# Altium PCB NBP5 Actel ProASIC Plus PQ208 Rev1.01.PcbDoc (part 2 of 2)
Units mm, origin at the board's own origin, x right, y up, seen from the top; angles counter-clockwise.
Board outline 69 x 80.99 mm, 2 copper layers (Top Layer, Bottom Layer); 65 components, 193 nets, 558 pads, 171 vias.
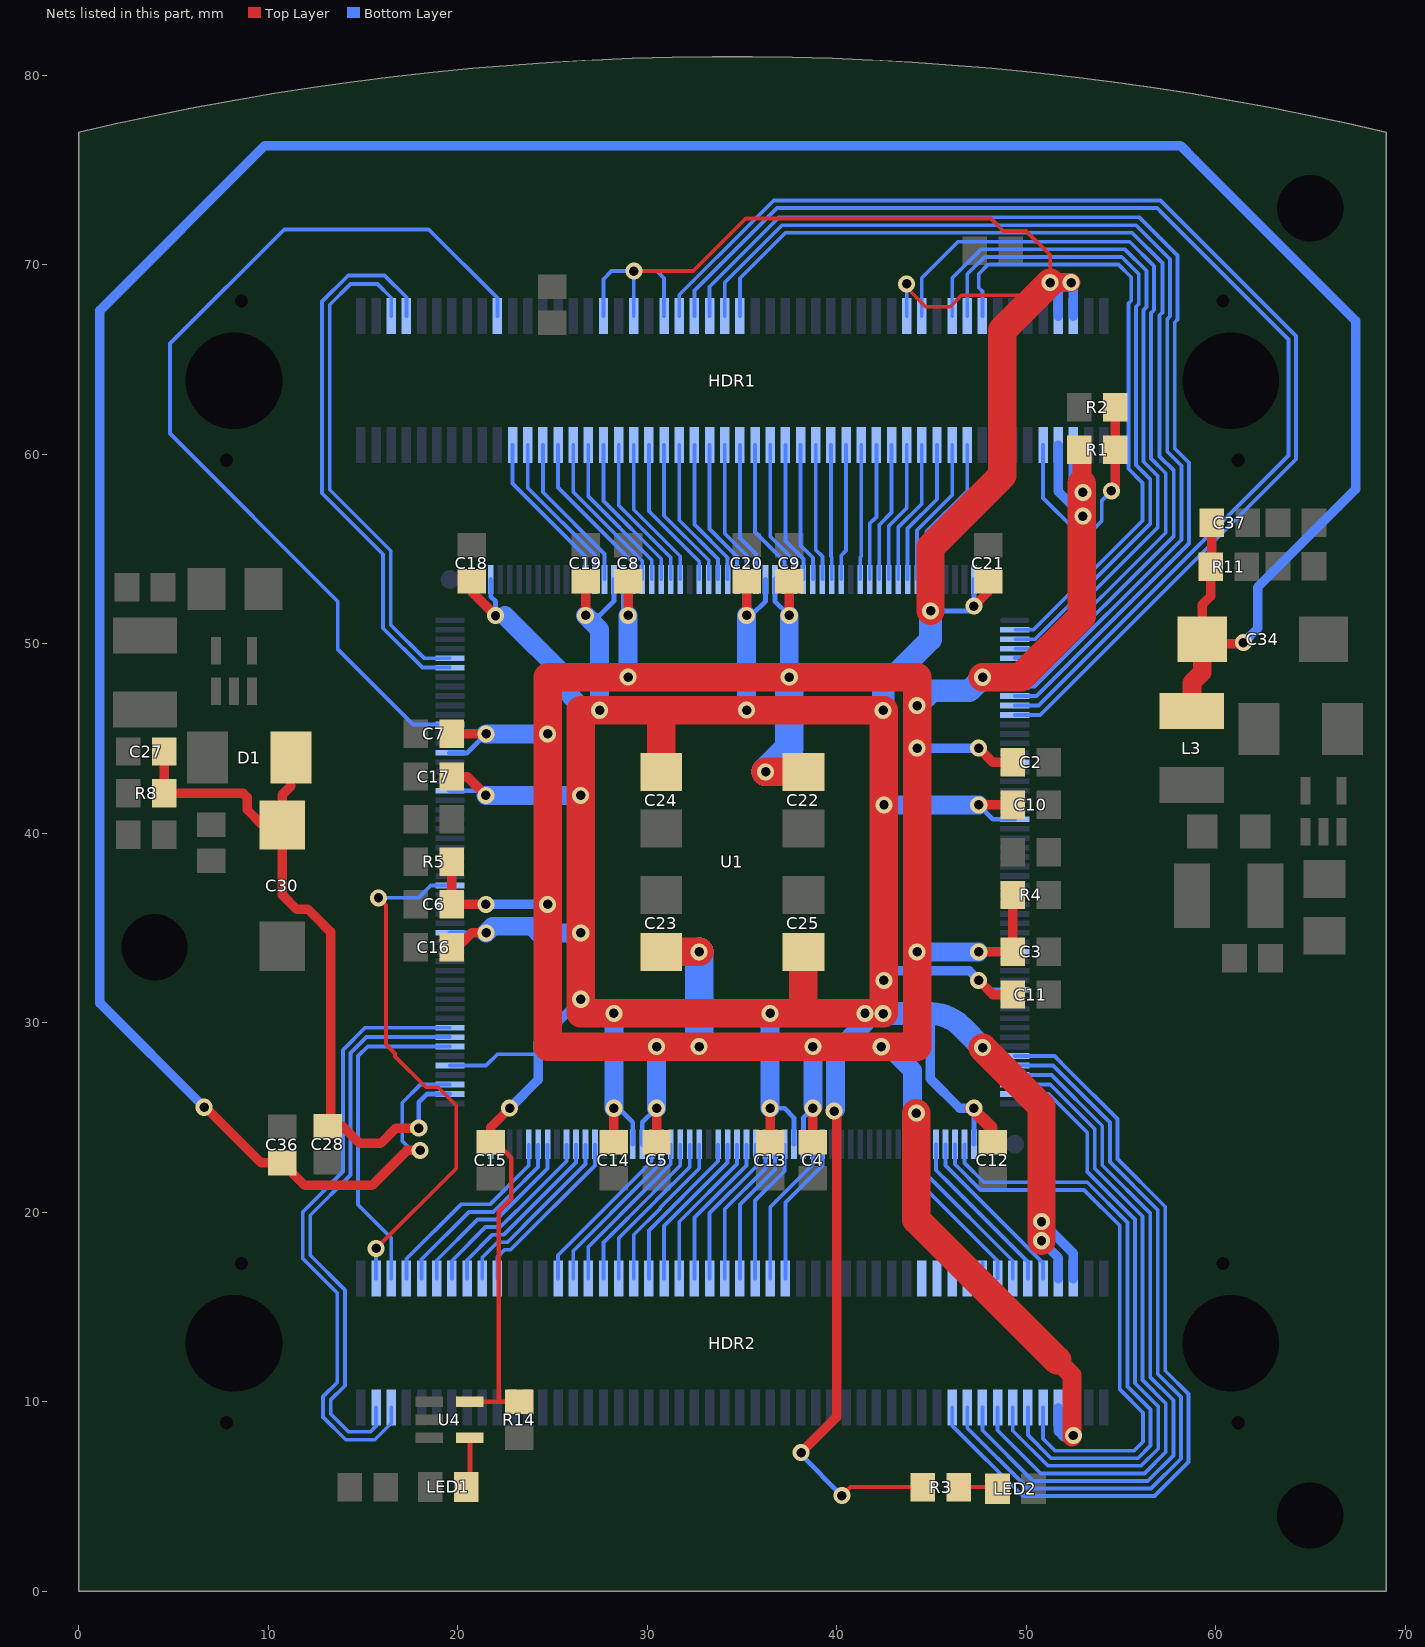
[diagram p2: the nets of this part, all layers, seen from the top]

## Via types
v1: diameter 0.9, hole 0.5, Top Layer to Bottom Layer, tented bottom, 171 vias

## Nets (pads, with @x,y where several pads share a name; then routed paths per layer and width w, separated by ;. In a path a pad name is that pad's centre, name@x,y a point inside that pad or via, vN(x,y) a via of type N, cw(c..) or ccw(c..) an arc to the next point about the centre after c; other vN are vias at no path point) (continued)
NetLED1_2: LED1.2 U4.4 | length 2.7
  Top Layer w0.25: LED1.2@20.457,5.512 20.65,5.705 U4.4@20.65,8.1
NetLED2_1: LED2.1 R3.2 | length 2.1
  Top Layer w0.2: R3.2@46.45,5.503 48.398,5.503 LED2.1@48.492,5.408
NEXUS_TCK: HDR1.82 U1.3 | length 35.2
  Bottom Layer w0.2: HDR1.82@46.9,67.3 46.9,69.525 47.8,70.425 55.05,70.425 55.95,69.525 55.95,67.947 55.8,67.797 55.8,59.45 56.55,58.7 56.55,56.325 50.475,50.25 U1.3@49.425,50.25
NEXUS_TDI: HDR1.84 U1.2 | length 34.1
  Bottom Layer w0.2: HDR1.84@47.7,68.2 HDR1.84@47.7,67.3 47.7,68.6 47.5,68.8 47.5,69.525 48,70.025 54.875,70.025 55.55,69.35 55.55,68.113 55.4,67.963 55.4,59.25 56.15,58.5 56.15,56.5 50.4,50.75 U1.2@49.425,50.75
NEXUS_TDO: HDR1.76 U1.5 | length 40.8
  Bottom Layer w0.2: HDR1.76@44.5,67.3 44.5,69.325 46.4,71.225 55.475,71.225 56.75,69.95 56.75,67.616 56.6,67.466 56.6,59.781 57.371,59.01 57.371,55.871 50.751,49.251 U1.5@49.4,49.251
NEXUS_TMS: HDR1.80 U1.4 | length 37.4
  Bottom Layer w0.2: HDR1.80@46.1,67.3 46.1,69.3 47.625,70.825 55.225,70.825 56.35,69.7 56.35,67.781 56.2,67.631 56.2,59.616 56.95,58.866 56.95,56.15 50.55,49.75 U1.4@49.425,49.75
RAM0_DATA0: HDR2.42 U1.79 | length 8.5
  Bottom Layer w0.2: HDR2.42@30.9,16.5 30.9,19.275 34.25,22.625 U1.79@34.25,23.575
RAM0_DATA1: HDR2.40 U1.80 | length 8.6
  Bottom Layer w0.2: HDR2.40@30.1,16.5 30.1,19.05 33.75,22.7 U1.80@33.75,23.575
RAM0_DATA2: HDR2.38 U1.82 | length 8.5
  Bottom Layer w0.2: HDR2.38@29.3,16.5 29.3,18.816 30.7,20.216 30.7,20.275 32.75,22.325 U1.82@32.75,23.575
RAM0_DATA3: HDR2.36 U1.83 | length 8.6
  Bottom Layer w0.2: HDR2.36@28.5,16.5 28.5,18.641 30.525,20.666 30.525,20.675 32.25,22.4 U1.83@32.25,23.575
RAM0_DATA4: HDR2.34 U1.84 | length 8.8
  Bottom Layer w0.2: HDR2.34@27.7,16.5 27.7,18.416 30.35,21.066 30.35,21.075 31.75,22.475 U1.84@31.75,23.575
RAM0_DATA5: HDR2.32 U1.85 | length 8.9
  Bottom Layer w0.2: HDR2.32@26.9,16.5 26.9,18.191 30.175,21.466 30.175,21.475 31.25,22.55 U1.85@31.25,23.575
RAM0_DATA6: HDR2.30 U1.86 | length 9
  Bottom Layer w0.2: HDR2.30@26.1,16.5 26.1,17.966 30,21.866 30,21.875 30.75,22.625 U1.86@30.75,23.575
RAM0_DATA7: HDR2.28 U1.87 | length 9.1
  Bottom Layer w0.2: HDR2.28@25.3,16.5 25.3,17.741 29.825,22.266 29.825,22.275 30.25,22.7 U1.87@30.25,23.575
RAM0_OE: HDR1.41 U1.180 | length 8
  Bottom Layer w0.2: HDR1.41@30.9,60.5 30.9,56.766 33.25,54.416 U1.180@33.25,53.425
RAM0_WE: HDR1.79 U1.202 | length 7.8
  Bottom Layer w0.2: U1.202@44.25,53.425 44.25,56 46.1,57.85 HDR1.79@46.1,60.5
RAM1_DATA0: HDR1.45 U1.182 | length 7.8
  Bottom Layer w0.2: HDR1.45@32.5,60.5 32.5,56.297 34.25,54.547 U1.182@34.25,53.425
RAM1_DATA1: HDR1.49 U1.184 | length 7.6
  Bottom Layer w0.2: HDR1.49@34.1,60.5 34.1,55.828 35.25,54.678 U1.184@35.25,53.425
RAM1_DATA2: HDR1.53 U1.188 | length 7.7
  Bottom Layer w0.2: HDR1.53@35.7,60.5 35.7,55.9 37.25,54.35 U1.188@37.25,53.425
RAM1_DATA3: HDR1.57 U1.190 | length 7.5
  Bottom Layer w0.2: HDR1.57@37.3,60.5 37.3,55.431 38.25,54.481 U1.190@38.25,53.425
RAM1_DATA4: HDR1.55 U1.189 | length 7.6
  Bottom Layer w0.2: HDR1.55@36.5,60.5 36.5,55.666 37.75,54.416 U1.189@37.75,53.425
RAM1_DATA5: HDR1.51 U1.185 | length 7.4
  Bottom Layer w0.2: HDR1.51@34.9,60.5 34.9,55.594 35.75,54.744 U1.185@35.75,53.425
RAM1_DATA6: HDR1.47 U1.183 | length 7.7
  Bottom Layer w0.2: HDR1.47@33.3,60.5 33.3,56.063 34.75,54.613 U1.183@34.75,53.425
RAM1_DATA7: HDR1.43 U1.181 | length 7.9
  Bottom Layer w0.2: HDR1.43@31.7,60.5 31.7,56.531 33.75,54.481 U1.181@33.75,53.425
RAM1_OE: HDR1.39 U1.179 | length 8.2
  Bottom Layer w0.2: HDR1.39@30.1,60.5 30.1,57 32.75,54.35 U1.179@32.75,53.425
RAM1_WE: HDR1.61 U1.192 | length 7.2
  Bottom Layer w0.2: HDR1.61@38.9,60.5 38.9,54.963 39.25,54.613 U1.192@39.25,53.425
RAM_ADDR0: HDR1.21 U1.167 | length 8.7
  Bottom Layer w0.2: HDR1.21@22.9,60.5 22.9,58.472 26.75,54.622 U1.167@26.75,53.425
RAM_ADDR1: HDR1.25 U1.169 | length 8.4
  Bottom Layer w0.2: HDR1.25@24.5,60.5 24.5,58.003 27.75,54.753 U1.169@27.75,53.425
RAM_ADDR2: HDR1.29 U1.173 | length 8.6
  Bottom Layer w0.2: HDR1.29@26.1,60.5 26.1,58.016 29.75,54.366 U1.173@29.75,53.425
RAM_ADDR3: HDR1.33 U1.175 | length 8.3
  Bottom Layer w0.2: HDR1.33@27.7,60.5 27.7,57.547 30.75,54.497 U1.175@30.75,53.425
RAM_ADDR4: HDR1.65 U1.194 | length 7.2
  Bottom Layer w0.2: U1.194@40.25,53.425 40.25,54.675 40.5,54.925 HDR1.65@40.5,60.5
RAM_ADDR5: HDR1.69 U1.197 | length 7.2
  Bottom Layer w0.2: U1.197@41.75,53.425 41.75,56.35 42.1,56.7 HDR1.69@42.1,60.5
RAM_ADDR6: HDR1.73 U1.199 | length 7.5
  Bottom Layer w0.2: U1.199@42.75,53.425 42.75,56.219 43.7,57.169 HDR1.73@43.7,60.5
RAM_ADDR7: HDR1.77 U1.201 | length 7.7
  Bottom Layer w0.2: U1.201@43.75,53.425 43.75,56.087 45.3,57.637 HDR1.77@45.3,60.5
RAM_ADDR8: HDR1.75 U1.200 | length 7.6
  Bottom Layer w0.2: U1.200@43.25,53.425 43.25,56.153 44.5,57.403 HDR1.75@44.5,60.5
RAM_ADDR9: HDR1.71 U1.198 | length 7.3
  Bottom Layer w0.2: U1.198@42.25,53.425 42.25,56.284 42.9,56.934 HDR1.71@42.9,60.5
RAM_ADDR10: HDR1.67 U1.196 | length 7.1
  Bottom Layer w0.2: U1.196@41.25,53.425 41.25,54.575 41.3,54.625 HDR1.67@41.3,60.5
RAM_ADDR11: HDR1.63 U1.193 | length 7.1
  Bottom Layer w0.2: HDR1.63@39.7,60.5 39.7,54.625 39.75,54.575 U1.193@39.75,53.425
RAM_ADDR12: HDR1.59 U1.191 | length 7.3
  Bottom Layer w0.2: HDR1.59@38.1,60.5 38.1,55.197 38.75,54.547 U1.191@38.75,53.425
RAM_ADDR13: HDR1.35 U1.176 | length 8.2
  Bottom Layer w0.2: HDR1.35@28.5,60.5 28.5,57.313 31.25,54.563 U1.176@31.25,53.425
RAM_ADDR14: HDR1.31 U1.174 | length 8.5
  Bottom Layer w0.2: HDR1.31@26.9,60.5 26.9,57.781 30.25,54.431 U1.174@30.25,53.425
RAM_ADDR15: HDR1.27 U1.172 | length 8.7
  Bottom Layer w0.2: HDR1.27@25.3,60.5 25.3,58.25 29.25,54.3 U1.172@29.25,53.425
RAM_ADDR16: HDR1.23 U1.168 | length 8.5
  Bottom Layer w0.2: HDR1.23@23.7,60.5 23.7,58.238 27.25,54.688 U1.168@27.25,53.425
RAM_CS: HDR1.37 U1.177 | length 8.1
  Bottom Layer w0.2: HDR1.37@29.3,60.5 29.3,57.078 31.75,54.628 U1.177@31.75,53.425
RED0: HDR1.6 U1.152 | length 27
  Bottom Layer w0.2: HDR1.6@16.5,67.3 16.5,68.275 15.775,69 14.35,69 13.25,67.9 13.25,58.134 16.469,54.915 16.469,51.006 18.225,49.25 U1.152@19.575,49.25
RED1: HDR1.8 U1.151 | length 29.4
  Bottom Layer w0.2: HDR1.8@17.3,67.3 17.3,68.3 16.15,69.45 14.225,69.45 12.85,68.075 12.85,57.95 16.069,54.731 16.069,50.831 18.15,48.75 U1.151@19.575,48.75
REF_CLK: HDR2.4 U1.128 | length 27.9
  Top Layer w0.2: v1(15.7,18.1) 19.925,22.325 19.925,25.634 18.959,26.6 18.325,26.6 16.7,28.225 16.7,28.391 16.225,28.866 16.225,36.2 v1(15.825,36.6)
  Bottom Layer w0.2: HDR2.4@15.7,16.5 v1(15.7,18.1) ; v1(15.825,36.6) 17.934,36.6 18.584,37.25 U1.128@19.575,37.25
SCL: HDR2.5 U1.113 | length 32.7
  Bottom Layer w0.2: HDR2.5@16.5,9.7 16.5,8.875 15.625,8 14.1,8 12.9,9.2 12.9,10.275 13.65,11.025 13.65,15.744 11.825,17.569 11.825,20.025 13.95,22.15 13.95,28.577 15.123,29.75 U1.113@19.575,29.75
SDA: HDR2.3 U1.112 | length 30.4
  Bottom Layer w0.2: HDR2.3@15.7,9.7 15.7,8.725 15.402,8.427 14.248,8.427 13.3,9.375 13.3,10.1 14.05,10.85 14.05,15.91 12.225,17.735 12.225,19.85 14.35,21.975 14.35,28.412 15.188,29.25 U1.112@19.575,29.25
SP0: HDR2.79 U1.47 | length 42.2
  Bottom Layer w0.2: HDR2.79@46.1,9.7 46.1,8.75 49.825,5.025 56.775,5.025 58.575,6.825 58.575,10.419 57.35,11.644 57.35,20.294 54.825,22.819 54.825,24.925 52.246,27.504 51.499,28.251 U1.47@49.4,28.251
SP1: HDR2.81 U1.48 | length 39.9
  Bottom Layer w0.2: HDR2.81@46.9,9.7 46.9,8.625 50.1,5.425 56.6,5.425 58.175,7 58.175,10.253 56.95,11.478 56.95,20.128 54.425,22.653 54.425,24.75 51.424,27.751 U1.48@49.4,27.751
SP2: HDR2.83 U1.49 | length 37.6
  Bottom Layer w0.2: HDR2.83@47.7,9.7 47.7,8.5 50.375,5.825 56.425,5.825 57.775,7.175 57.775,10.088 56.55,11.313 56.55,19.962 54.025,22.487 54.025,24.575 51.349,27.251 U1.49@49.4,27.251
SP3: HDR2.85 U1.50 | length 35.3
  Bottom Layer w0.2: HDR2.85@48.5,9.7 48.5,8.5 50.775,6.225 56.25,6.225 57.375,7.35 57.375,9.922 56.15,11.147 56.15,19.797 53.625,22.322 53.625,24.4 51.274,26.751 U1.50@49.4,26.751
SP4: HDR2.87 U1.51 | length 33
  Bottom Layer w0.2: HDR2.87@49.3,9.7 49.3,8.475 51.15,6.625 56.075,6.625 56.975,7.525 56.975,9.756 55.75,10.981 55.75,19.631 53.225,22.156 53.225,24.225 51.199,26.251 U1.51@49.4,26.251
SP5: HDR2.89 U1.54 | length 31.9
  Bottom Layer w0.2: U1.54@46.75,23.601 46.75,22.607 47.769,21.588 53.227,21.588 55.35,19.465 55.35,10.816 56.575,9.591 56.575,7.7 55.9,7.025 51.325,7.025 50.1,8.25 HDR2.89@50.1,9.7
SP6: HDR2.91 U1.55 | length 30.4
  Bottom Layer w0.2: U1.55@46.25,23.601 46.25,22.541 47.603,21.188 53.062,21.188 54.95,19.3 54.95,10.65 56.175,9.425 56.175,7.9 55.7,7.425 51.525,7.425 50.9,8.05 HDR2.91@50.9,9.7
SP7: HDR2.92 U1.56 | length 9.2
  Bottom Layer w0.2: U1.56@45.75,23.601 45.75,22.475 50.9,17.325 HDR2.92@50.9,16.5
SP8: HDR2.90 U1.57 | length 9.4
  Bottom Layer w0.2: U1.57@45.25,23.601 45.25,22.225 45.985,21.49 ; 45.75,21.725 45.985,21.49 ; HDR2.90@50.1,16.5 50.1,17.375 45.985,21.49
SP9: HDR2.88 U1.58 | length 9
  Bottom Layer w0.2: U1.58@44.75,23.601 44.75,22 49.3,17.45 HDR2.88@49.3,16.5
SP10: HDR2.86 U1.59 | length 8.9
  Bottom Layer w0.2: U1.59@44.25,23.601 44.25,21.7 48.5,17.45 HDR2.86@48.5,16.5
SP11: HDR2.84 | length 0.8
  Bottom Layer w0.2: HDR2.84@47.7,16.5 HDR2.84@47.7,17.341
SP12: HDR2.82
SP13: HDR2.80
SP14: HDR2.78
SP15: HDR2.76
SPI_CLK: HDR1.46 U1.10 | length 63.4
  Bottom Layer w0.2: HDR1.46@32.5,67.3 32.5,68.65 36.277,72.427 36.85,73 56.925,73 57.173,72.752 63.85,66.075 63.85,59.95 50.651,46.751 U1.10@49.4,46.751
SPI_DIN: HDR1.44 U1.11 | length 66.3
  Bottom Layer w0.2: HDR1.44@31.7,67.3 31.7,68.425 35.6,72.325 ; 35.134,71.859 35.143,71.859 36.684,73.4 57.1,73.4 64.25,66.25 64.25,59.75 50.751,46.251 U1.11@49.4,46.251
SPI_DOUT: HDR1.50 U1.8 | length 54.5
  Bottom Layer w0.2: HDR1.50@34.1,67.3 34.1,69.075 36.815,71.79 37.125,72.1 55.8,72.1 57.6,70.3 57.6,67.291 57.459,67.15 ; U1.8@49.4,47.751 50.451,47.751 58.2,55.5 58.2,59.4 57.45,60.15 57.45,67.15 57.455,67.155
SPI_MODE: HDR1.52 U1.7 | length 52.2
  Bottom Layer w0.2: HDR1.52@34.9,67.3 34.9,69.3 37.3,71.7 55.6,71.7 57.2,70.1 57.2,67.5 57.05,67.35 57.05,59.897 57.8,59.147 57.8,55.7 50.351,48.251 U1.7@49.4,48.251
SPI_SEL: HDR1.48 U1.9 | length 56.7
  Bottom Layer w0.2: HDR1.48@33.3,67.3 33.3,68.85 36.677,72.227 36.964,72.514 55.986,72.514 58,70.5 58,67.125 57.85,66.975 57.85,60.316 58.6,59.566 58.6,55.3 50.551,47.251 U1.9@49.4,47.251
SW0: HDR2.44 U1.78 | length 8.3
  Bottom Layer w0.2: HDR2.44@31.7,16.5 31.7,19.509 34.75,22.559 U1.78@34.75,23.575
SW1: HDR2.46 U1.77 | length 8.2
  Bottom Layer w0.2: HDR2.46@32.5,16.5 32.5,19.725 35.25,22.475 U1.77@35.25,23.575
SW2: HDR2.48 U1.76 | length 8.1
  Bottom Layer w0.2: HDR2.48@33.3,16.5 33.3,19.959 35.75,22.409 U1.76@35.75,23.575
SW3: HDR2.50 U1.75 | length 8
  Bottom Layer w0.2: HDR2.50@34.1,16.5 34.1,20.175 36.25,22.325 U1.75@36.25,23.575
SW4: HDR2.52 U1.74 | length 7.8
  Bottom Layer w0.2: HDR2.52@34.9,16.5 34.9,20.409 36.75,22.259 U1.74@36.75,23.575
SW5: HDR2.54 U1.73 | length 7.7
  Bottom Layer w0.2: HDR2.54@35.7,16.5 35.7,20.625 37.25,22.175 U1.73@37.25,23.575
SW6: HDR2.56 U1.70 | length 8
  Bottom Layer w0.2: HDR2.56@36.5,16.5 36.5,20.291 38.75,22.54 U1.70@38.75,23.601
SW7: HDR2.58 U1.69 | length 7.9
  Bottom Layer w0.2: HDR2.58@37.3,16.5 37.3,20.525 39.25,22.475 U1.69@39.25,23.575
SWC0: HDR2.18 U1.94 | length 9.6
  Bottom Layer w0.2: HDR2.18@21.3,16.5 21.3,17.625 22.1,18.425 22.634,18.425 23.475,19.266 23.475,19.275 26.75,22.55 U1.94@26.75,23.575
SWC1: HDR2.16 U1.95 | length 9.8
  Bottom Layer w0.2: HDR2.16@20.5,16.5 20.5,17.475 21.85,18.825 22.4,18.825 22.42,18.845 ; 22.441,18.825 23.525,19.909 23.534,19.909 26.25,22.625 U1.95@26.25,23.575
SWC2: HDR2.14 U1.96 | length 10
  Bottom Layer w0.2: HDR2.14@19.7,16.5 19.7,17.45 21.475,19.225 22.25,19.225 23.1,20.075 23.125,20.075 25.75,22.7 U1.96@25.75,23.575
SWC3: HDR2.6 U1.111 | length 17.5
  Bottom Layer w0.2: HDR2.6@16.5,16.5 16.5,18.65 14.75,20.4 14.75,28.246 15.254,28.75 U1.111@19.575,28.75
SWR0: HDR2.20 U1.93 | length 9.4
  Bottom Layer w0.2: HDR2.20@22.1,16.5 22.1,17.65 22.475,18.025 22.8,18.025 27.25,22.475 U1.93@27.25,23.575
SWR1: HDR2.12 U1.98 | length 10.1
  Bottom Layer w0.2: HDR2.12@18.9,16.5 18.9,17.475 21.05,19.625 22.05,19.625 22.9,20.475 24.75,22.325 U1.98@24.75,23.575
SWR2: HDR2.10 U1.99 | length 10.4
  Bottom Layer w0.2: HDR2.10@18.1,16.5 18.1,17.525 20.6,20.025 21.884,20.025 22.725,20.866 22.725,20.875 24.25,22.4 U1.99@24.25,23.575
SWR3: HDR2.8 U1.100 | length 10.6
  Bottom Layer w0.2: HDR2.8@17.3,16.5 17.3,17.55 20.175,20.425 21.709,20.425 22.55,21.266 22.55,21.275 23.75,22.475 U1.100@23.75,23.575
TEST: HDR1.81 U1.203 | length 8
  Bottom Layer w0.2: U1.203@44.75,53.425 44.75,55.934 46.9,58.084 HDR1.81@46.9,60.5
VCC: C10.1 C11.2 C12.2 C13.2 C14.2 C15.2 C16.2 C17.2 C18.2 C19.2 C20.2 C21.2 C24.1 C25.1 HDR1.34 HDR1.38 HDR1.42 HDR1.74 HDR1.94 HDR1.96 HDR2.94 HDR2.96 R3.1 R14.2 U1.22 U1.40 U1.53 U1.72 U1.89 U1.104 U1.109 U1.123 U1.138 U1.157 U1.170 U1.186 U1.208 U4.5 | length 341.4
  Top Layer w0.2: v1(29.3,69.675) 32.434,69.675 35.209,72.45 48.15,72.45 48.8,71.8 50,71.8 51.275,70.525 v1(51.275,69.075) ; v1(40.275,5.05) 40.728,5.503 R3.1@44.55,5.503 ; v1@43.7,68.8 44.7,67.8 46,67.8 46.6,68.4 50.1,68.4 ; v1(52.375,69.075) v1@52.5,69.2
  Top Layer w0.25: U4.5@20.65,10 R14.2@23.247,10 ; C15.2@21.747,23.7 22,23.7 22.825,22.875 22.825,20.725 22.172,20.072 22.172,10.078 22.095,10
  Top Layer w0.5: C16.2@19.7,34.003 20.003,34.003 20.75,34.75 v1(21.5,34.75) ; C17.2@19.7,43.003 20.497,43.003 v1(21.497,42.003) ; C18.2@20.753,53.3 20.753,52.747 v1(22,51.5) ; C15.2@21.747,23.7 21.747,24.497 v1(22.75,25.5) ; v1(26.753,51.503) C19.2@26.753,53.3 ; C14.2@28.247,23.7 v1(28.247,25.497) ; v1(35.253,51.503) C20.2@35.253,53.3 ; C13.2@36.497,23.7 v1(36.497,25.497) ; v1(38.125,7.325) 40,9.2 40,25.225 v1(39.875,25.35) ; v1@47,25.5 C12.2@48.247,24.253 ; v1(47.25,25.5) 48.247,24.503 C12.2@48.247,23.7 ; v1(47.25,52) 48.003,52.753 C21.2@48.003,53.3 ; v1(47.5,32.25) 48.253,31.497 C11.2@49.3,31.497 ; v1(47.503,41.503) C10.1@49.3,41.503
  Top Layer w1: v1(51.275,69.075) v1(52.375,69.075)
  Top Layer w1.5: C24.1@30.75,43.25 30.75,46.5 ; 38.25,30.5 C25.1@38.25,33.75 ; v1(44.958,51.742) 44.958,55.098 48.75,58.89 48.75,66 48.75,66.55 v1(51.275,69.075) ; v1(47.708,28.692) 50.815,25.589 v1(50.815,18.502) ; 26.5,30.5 42.5,30.5 42.5,46.5 26.5,46.5 26.5,30.5
  Bottom Layer w0.2: U1.109@19.6,27.751 21.501,27.751 22.1,28.35 24.25,28.35 ; HDR1.34@27.7,67.3 27.7,69.25 28.125,69.675 30.525,69.675 30.9,69.3 HDR1.42@30.9,67.3 ; HDR1.38@29.3,67.3 v1(29.3,69.675) ; HDR1.74@43.7,67.3 v1(43.7,69)
  Bottom Layer w0.25: U1.138@19.575,42.25 v1@21.25,42.25 ; U1.123@19.6,34.75 v1(21.5,34.75) ; U1.104@21.75,23.601 21.75,24.5 v1(22.75,25.5) ; U1.157@21.75,53.401 21.75,52.5 22,52.25 v1(22,51.5) ; v1(26.753,51.503) 27.503,51.503 28.25,52.25 U1.170@28.25,53.401 ; v1(28.247,25.497) 28.503,25.497 29.25,24.75 U1.89@29.25,23.601 ; v1(35.253,51.503) 35.503,51.503 36.25,52.25 U1.186@36.25,53.401 ; v1(36.497,25.497) 37.253,25.497 37.75,25 U1.72@37.75,23.601 ; v1(38.125,7.325) 38.125,7.2 v1(40.275,5.05) ; v1(44.958,51.742) 46.992,51.742 v1(47.25,52) U1.208@47.25,53.401 ; U1.53@47.25,23.601 v1(47.25,25.5) ; v1(47.5,32.25) 48,31.75 U1.40@49.4,31.75 ; v1(47.503,41.503) 48.255,40.75 U1.22@49.4,40.75
  Bottom Layer w0.5: v1(22,51.5) 22.5,51.5 ; v1@22.788,25.538 24.25,27 24.25,29 v1(26.5,31.25) ; v1(39.875,25.35) v1@39.875,25.422 ; v1(42.5,32.25) 43,32.75 47,32.75 v1(47.5,32.25) ; 44.955,30.492 44.955,27.045 46.5,25.5 v1(47.25,25.5) ; v1(50.815,18.502) 51.7,17.617 HDR2.94@51.7,16.5 ; v1(50.815,19.518) 52.5,17.833 HDR2.96@52.5,16.5 ; v1(51.275,69.075) 51.7,68.65 HDR1.94@51.7,67.3 ; v1(52.375,69.075) 52.5,68.95 HDR1.96@52.5,67.3
  Bottom Layer w1: v1(21.497,42.003) v1(26.497,42.003) ; v1(21.5,34.75) 21.85,35.1 23.925,35.1 24.275,34.75 v1(26.5,34.75) ; 22.5,51.5 25.95,48.05 25.95,47.275 26.725,46.5 v1(27.5,46.5) 27.5,50.755 v1(26.753,51.503) ; v1(28.247,25.497) v1(28.247,30.497) ; v1(35.253,46.503) v1(35.253,51.503) ; v1(36.497,25.497) v1(36.497,30.497) ; v1@39.947,25.422 39.947,28.447 41.5,30 v1(41.5,30.5) v1@42.45,30.5 ; v1(42.503,41.503) v1(47.503,41.503)
  Bottom Layer w1.2: v1@42.458,30.498 44.955,30.492 cw(c44.955,28.192) 46.582,29.819 v1(47.708,28.692) ; v1(42.458,46.492) 42.458,47.733 44.958,50.233 v1(44.958,51.742)
  other v1: 42.458,30.492
VCCINT: C2.2 C3.2 C4.2 C5.2 C6.2 C7.2 C8.2 C9.2 C22.1 C23.1 HDR1.93 HDR1.95 HDR2.93 HDR2.95 R1.1 R4.1 R5.1 U1.16 U1.36 U1.71 U1.88 U1.126 U1.142 U1.171 U1.187 | length 210.2
  Top Layer w0.5: R5.1@19.7,38.497 C6.2@19.7,36.253 v1(21.497,36.253) ; C7.2@19.7,45.253 19.702,45.25 v1(21.5,45.25) ; v1(29.003,51.503) C8.2@29.003,53.3 ; C5.2@30.497,23.7 v1(30.497,25.497) ; v1(37.503,51.503) C9.2@37.503,53.3 ; C4.2@38.747,23.7 v1(38.747,25.497) ; v1(47.5,44.5) 48.253,43.747 C2.2@49.3,43.747 ; v1(47.503,33.747) C3.2@49.3,33.747 R4.1@49.3,36.753
  Top Layer w1: 51.638,12.193 52.425,11.406 v1@52.425,8.15 ; 52.95,58.45 R1.1@52.95,59.85
  Top Layer w1.5: C23.1@30.75,33.75 v1(32.75,33.75) ; v1(36.25,43.25) C22.1@38.25,43.25 ; v1(44.208,25.242) 44.208,19.623 51.638,12.193 ; v1(47.708,48.242) 49.72,48.242 52.95,51.473 52.95,58.45 ; 24.75,28.75 44.25,28.75 44.25,48.25 24.75,48.25 24.75,28.75
  Bottom Layer w0.25: U1.126@19.575,36.25 v1@21.495,36.25 ; U1.142@19.575,44.25 20.5,44.25 v1(21.5,45.25) ; U1.171@28.75,53.425 28.75,51.755 v1(29.003,51.503) ; U1.88@29.75,23.575 29.75,24.75 v1(30.497,25.497) ; U1.187@36.75,53.425 36.75,52.255 v1(37.503,51.503) ; U1.71@38.25,23.575 38.25,25 v1(38.747,25.497) ; v1(47.5,44.5) 48.25,43.75 U1.16@49.425,43.75 ; v1@47.505,33.75 U1.36@49.425,33.75
  Bottom Layer w0.5: v1(21.497,36.253) v1(24.747,36.253) ; v1(38.747,25.497) v1@38.747,25.576 ; v1(44.25,44.5) v1(47.5,44.5) ; HDR2.93@51.7,9.7 51.7,8.45 52,8.15 52.425,8.15 v1(52.5,8.225) HDR2.95@52.5,9.7 ; HDR1.93@51.7,60.5 51.7,58.05 v1(53,56.75) ; HDR1.95@52.5,60.5 52.5,58.5 v1(53,58)
  Bottom Layer w1: v1(21.5,45.25) v1(24.75,45.25) ; v1(29.003,48.253) v1(29.003,51.503) ; v1(30.497,25.497) v1(30.497,28.747) ; v1(37.503,48.253) v1(37.503,51.503) ; v1@38.747,25.576 v1(38.747,28.747) ; v1(42.358,28.742) 42.758,28.742 44,27.5 44,25.45 v1(44.208,25.242) ; v1(44.253,33.747) v1(47.503,33.747)
  Bottom Layer w1.2: v1(44.25,46.75) 45.025,47.525 47,47.525 v1(47.708,48.242)
  Bottom Layer w1.5: v1(32.75,28.75) v1(32.75,33.75) ; v1(36.25,43.25) 37.503,44.503 v1(37.503,48.253)
VDRIVE: HDR1.20 U1.145 | length 49.6
  Bottom Layer w0.2: U1.145@19.575,45.75 17.65,45.75 13.669,49.731 13.669,52.256 4.825,61.1 4.825,65.85 10.85,71.875 18.475,71.875 22.1,68.25 HDR1.20@22.1,67.3
VPN: C34.2 C36.1 C37.1 L3.2 R11.1 U1.107 | length 169.9
  Top Layer w0.5: v1(6.625,25.55) 6.7,25.55 9.641,22.609 C36.1@10.747,22.609 11.932,21.425 15.475,21.425 17.325,23.275 v1(18.025,23.275) ; R11.1@59.75,54.078 59.75,52.525 59.3,52.075 59.3,50 61.4,50 v1(61.475,50.075) ; R11.1@59.8,54.128 C37.1@59.8,56.403
  Top Layer w1: L3.2@58.75,46.45 58.75,47.95 59.3,48.5 C34.2@59.3,50
  Bottom Layer w0.2: v1(18.025,23.275) 17.575,23.275 17.075,23.775 17.075,25.784 18.041,26.75 U1.107@19.575,26.75
  Bottom Layer w0.5: v1(6.625,25.55) 1.125,31.05 1.125,67.6 9.825,76.3 58.15,76.3 58.92,75.53 67.4,67.05 67.4,58.175 66.478,57.253 62.225,53 62.225,50.825 v1(61.475,50.075)
VPP: C27.1 C28.1 C30.1 D1.2 R8.1 U1.106 | length 38.5
  Top Layer w0.5: C27.1@4.525,44.322 R8.1@4.525,42.122 8.678,42.122 8.9,41.9 8.9,41.25 C30.1@9.7,40.45 ; D1.2@11.375,43.825 D1.2@11.2,44 11.2,42.5 10.75,42.05 10.75,36.75 11.5,36 12.1,36 12.5,35.6 13.3,34.8 13.3,24.698 C28.1@13.153,24.55 13.925,24.55 14.825,23.65 15.95,23.65 16.75,24.45 v1(17.95,24.45)
  Bottom Layer w0.25: v1(17.95,24.45) 17.95,25.8 18.4,26.25 U1.106@19.575,26.25
VREF: HDR1.91 R1.2 R2.1 | length 13.2
  Top Layer w0.5: v1(54.5,58.075) 54.588,58.162 54.7,58.275 R1.2@54.7,60.253 R2.1@54.7,62.497
  Bottom Layer w0.2: HDR1.91@50.9,60.5 50.9,57.7 52.7,55.9 53.4,55.9 54,56.5 54,57.575 v1(54.5,58.075)
pads on no net: HDR1.MH1 HDR1.MH2 HDR1.MH3 HDR1.MH4 HDR1.MH5 HDR1.MH6 HDR2.MH1 HDR2.MH2 HDR2.MH3 HDR2.MH4 HDR2.MH5 HDR2.MH6 U1.6 U1.26 U1.28 U1.129 U1.132 U1.FID1 U1.FID2 U4.1

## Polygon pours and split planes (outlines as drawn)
GND on Top Layer "Top Layer-GND" (solid, remove dead copper, pour order 1000): 0,0 0,81 69,81 69,0
GND on Bottom Layer "Bottom Layer-GND" (solid, remove dead copper, pour order 1001): 0,0 0,81 69,81 69,0

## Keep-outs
Keep-Out Layer:
  the board outline again, w0.8

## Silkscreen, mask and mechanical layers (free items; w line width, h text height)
Top Overlay:
  circle w0.127: c4,34 r2.5
  circle w0.127: c65,4 r2.5
  circle w0.127: c65,73 r2.5
  lines w0.127: 0,1.5 1.5,1.5 1.5,0 ; 0,22.3 1.5,22.3 1.5,23.4 0,23.4 ; 0.001,53.6 1.501,53.6 1.501,54.7 0.001,54.7 ; 0,75.5 1.5,75.5 1.5,77.3 ; 15.7,79.8 15.7,78.1 17,78.1 17,79.9 ; 49.7,80.2 49.7,78.7 51,78.7 51,80.1 ; 52.1,41.8 53.1,41.8 ; 67.5,0 67.5,1.5 69,1.5 ; 67.5,77.3 67.5,75.5 69,75.5 ; 68.999,22.3 67.5,22.3 67.5,23.4 69,23.4 ; 69,53.6 67.501,53.6 67.501,54.7 69.001,54.7
Bottom Overlay:
  drawing of 853 lines, arcs and shapes, not listed
  text "REV 1.01" at 47.6,76.5 h1.3
  text "NBP5" at 54.5,76.5 h1.3
  text "1" at 13.97,58.42 h1
  text "1" at 14.224,7.62 h1
PCB Boundary:
  the board outline again, w0.25
  text "PCB boundary coincides with centre-line of tracks and arc" at 0,-12 h0.75
Gerber ID:
  text ".Layer_Name" at 0,-6 h0.75
Printout ID:
  text ".Printout_Name" at 0,-10 h0.75
Design Information:
  drawing of 713 lines, arcs and shapes, not listed
  text "NBP5 REV 1.01" at 317.627,202.041 h1.27
  text "DESIGN INFORMATION" at 261.62,201.914 h1.52
  text "BOARD NAME:" at 299.212,201.914 h1.52
  text "BOARD TECHNOLOGY" at 261.62,199.374 h1.52
  text "BOARD SIZE (REFER ALSO PROFILING INFORMATION)" at 309.88,199.374 h1.27
  text "69.00mm" at 312.6,197.1 h1.52
  text "11.811" at 277.419,197.012 h1.52
  text "81.00mm" at 335.6,197 h1.52
  text "7.874" at 291.389,196.885 h1.52
  text "7.874" at 264.446,196.834 h1.52
  text "X" at 328.549,196.326 h1.78
  text "(MIN. TRACK/   PADS  /   CLEARANCE     IN 0.001'')" at 260.096,194.294 h1.27
  text "MINIMUM ANNULAR RING 0.05MM (0.002'') EXTERNAL PER IPC-2221 CLASS 3 LEVEL C AND IS THE" at 261.62,191.754 h1.27
  text "MANUFACTURING REGISTRATION ALLOWANCE" at 261.62,189.468 h1.27
  text "LAND SIZE CALCULATION MINIMUM - NOMINAL HOLE SIZE + 0.508MM (0.020'')" at 261.62,186.674 h1.27
  text "AS INSTRUCTED" at 347.65,182.28 h1.52
  text "X" at 299.263,182.153 h1.52
  text "CIRCUIT TYPE:" at 261.62,182.102 h1.52
  text "SS" at 284.48,182.102 h1.27
  text "DS" at 302.26,182.102 h1.27
  text "X" at 316.865,182.102 h1.52
  text "PTH" at 320.04,182.102 h1.27
  text "ML" at 330.962,182.102 h1.27
  text "No. OFF" at 337.82,182.102 h1.27
  text "FINGER CONNECTOR DIM PER:" at 261.62,179.054 h1.52
  text "AS SHOWN" at 337.82,179.054 h1.27
  text "No. OFF TOTAL" at 278.384,176.26 h1.52
  text "ONE SIDE" at 320.04,176.26 h1.27
  text "BOTH SIDES" at 337.82,176.006 h1.27
  text "VIAS:" at 261.62,173.339 h1.52
  text "NONE" at 273.05,173.339 h1.14
  text "X" at 281.432,173.339 h1.52
  text "FEED THRU'" at 284.48,173.339 h1.14
  text "X" at 299.212,173.339 h1.52
  text "TENTED (On BOTTOM side; via holes uncovered on TOP side)" at 302.26,173.339 h1.14
  text "UNIQUE DRILL" at 284.48,170.291 h1.14
  text "2 SIZE" at 302.26,170.291 h1.14
  text "BLIND LAYER SEQUENCE" at 320.04,170.291 h1.14
  text "Layer Stack Manager (Protel)" at 297.053,168.005 h1.27
  text "X" at 334.772,168.005 h1.52
  text "AS SHOWN" at 337.82,168.005 h1.27
  text "LAYER CONSTRUCTION PER:" at 261.62,167.878 h1.52
  text "Protel" at 342.646,165.338 h1.27
  text "(PFW)" at 352.933,165.211 h1.27
  text "ARTWORK:" at 261.62,165.084 h1.52
  text "MANUAL" at 284.48,165.084 h1.27
  text "DIGITISED" at 302.26,165.084 h1.27
  text "X" at 316.992,165.084 h1.52
  text "CAD" at 320.04,165.084 h1.27
  text "TYPE" at 330.962,165.084 h1.27
  text "ARTWORK/PATTERN MASTER LIST" at 261.62,160.385 h1.52
  text "DESCRIPTION" at 262.89,157.972 h1.27
  text "DRAWING No./CAD FILE REF." at 281.559,157.972 h1.27
  text "LAYER NAME" at 322.834,157.972 h1.27
  text "GERBER FILE REF" at 343.586,157.896 h1.27
  text "PCB FILE" at 261.366,155.432 h1.27
  text "BOCD_Actel_APA_NBP5_1_01" at 281.737,155.356 h1.27
  text "PcbDoc" at 312.979,155.356 h1.02
  text "Top Paste Mask" at 321.158,152.892 h1.02
  text "GTP" at 363.779,152.816 h1.27
  text "GERBER FILE" at 261.366,152.765 h1.27
  text "GTO" at 363.728,150.327 h1.27
  text "Top Overlay" at 321.158,150.301 h1.02
  text "GERBER FILE" at 261.366,150.225 h1.27
  text "Top Solder Mask" at 321.158,147.863 h1.02
  text "GTS" at 363.779,147.736 h1.27
  text "GERBER FILE" at 261.366,147.685 h1.27
  text "TOP LAYER" at 321.158,145.272 h1.02
  text "GTL" at 363.779,145.196 h1.27
  text "GERBER FILE" at 261.366,145.145 h1.27
  text "BOTTOMLAYER" at 321.158,142.732 h1.02
  text "GBL" at 363.779,142.656 h1.27
  text "GERBER FILE" at 261.366,142.605 h1.27
  text "Bottom Solder Mask" at 321.158,140.243 h1.02
  text "GBS" at 363.779,140.116 h1.27
  text "GERBER FILE" at 261.366,140.065 h1.27
  text "Bottom Overlay" at 321.158,137.652 h1.02
  text "GBO" at 363.779,137.576 h1.27
  text "GERBER FILE" at 261.366,137.525 h1.27
  text "Bottom Paste Mask" at 321.158,135.163 h1.02
  text "GBP" at 363.779,135.036 h1.27
  text "GERBER FILE" at 261.366,134.985 h1.27
  text "PCB Boundary" at 321.158,132.572 h1.02
  text "GM1" at 363.779,132.496 h1.27
  text "GERBER FILE" at 261.366,132.445 h1.27
  text "APERTURE LIST" at 261.366,130.032 h1.27
  text "APR" at 313.979,129.956 h1.27
  text "DRILL REPORT" at 261.366,127.492 h1.27
  text "DRR" at 313.979,127.416 h1.27
  text "EXCELLON DRILL" at 261.366,124.952 h1.27
  text "TXT" at 313.979,124.876 h1.27
  text "MATERIAL:" at 261.62,99.298 h1.52
  text "GLASS FIBRE EPOXY RESIN NEMA GRADE FR4 (MIL-S-13949H)" at 287.274,99.044 h1.27
  text "X" at 284.607,98.917 h1.52
  text "THICKNESS:" at 269.494,96.123 h1.27
  text "0.8mm" at 287.274,96.123 h1.27
  text "1.2mm" at 304.927,96.123 h1.27
  text "1.6mm" at 322.58,96.123 h1.27
  text "2.4mm" at 340.36,96.123 h1.27
  text "3.2mm" at 358.14,96.123 h1.27
  text "X" at 320.167,95.996 h1.52
  text "TOLERANCE:" at 269.367,93.075 h1.27
  text "IN A/W IPC-D-300G CLASS" at 287.02,93.075 h1.27
  text "3 LEVEL B" at 321.945,93.075 h1.27
  text "OTHER +/-" at 340.36,93.075 h1.27
  text "X" at 284.607,92.948 h1.52
  text "BOW & TWIST:" at 266.954,90.027 h1.27
  text "IN A/W IPC-D-300G CLASS" at 287.02,90.027 h1.27
  text "3 LEVEL B" at 321.945,90.027 h1.27
  text "AS SHOWN" at 340.487,89.9 h1.27
  text "X" at 284.607,89.773 h1.52
  text "COPPER THICKNESS (FINISHED)" at 269.367,86.725 h1.27
  text "OUTER:" at 274.193,84.439 h1.27
  text "18um" at 287.274,84.439 h1.27
  text "35um" at 314.325,84.439 h1.27
  text "70um" at 340.614,84.439 h1.27
  text "X" at 311.582,84.236 h1.52
  text "INNER SIGNAL:" at 265.811,81.391 h1.27
  text "18um" at 287.274,81.391 h1.27
  text "35um" at 314.325,81.391 h1.27
  text "70um" at 340.614,81.391 h1.27
  text "INNER PWR:" at 269.494,78.343 h1.27
  text "18um" at 287.274,78.343 h1.27
  text "35um" at 314.325,78.343 h1.27
  text "70um" at 340.614,78.343 h1.27
  text "STRUCTURE:" at 261.62,75.295 h1.52
  text "REFER" at 287.274,75.295 h1.27
  text "AS PER DRAWING No." at 287.147,72.12 h1.27
  text "AS SHOWN" at 340.487,72.12 h1.27
  text "X" at 337.947,71.993 h1.52
  text "DRILLING:" at 261.62,69.326 h1.52
  text "VIEWED FROM:" at 266.573,67.04 h1.27
  text "COMPONENT SIDE" at 287.274,67.04 h1.14
  text "SOLDER SIDE" at 314.071,67.04 h1.14
  text "X" at 284.607,66.786 h1.52
  text "REFERENCE:" at 268.859,63.992 h1.27
  text "AS SHOWN" at 287.147,63.865 h1.14
  text "PATTERN MASTER LIST" at 314.198,63.865 h1.14
  text "X" at 337.947,63.865 h1.52
  text "NC_DRILL FILES" at 340.487,63.865 h1.14
  text "X" at 284.607,63.738 h1.52
  text "PTH MINIMUM COPPER THICKNESS:" at 274.701,60.944 h1.27
  text "20um" at 314.325,60.944 h1.27
  text "X" at 311.658,60.817 h1.52
  text "OTHER" at 340.487,60.817 h1.27
  text "NPTH:" at 275.209,57.896 h1.27
  text "TENTED" at 287.147,57.769 h1.14
  text "X" at 311.658,57.769 h1.52
  text "PADS REMOVED" at 314.198,57.769 h1.14
  text "REMOVE PADS" at 340.487,57.769 h1.14
  text "X" at 284.607,57.642 h1.52
  text "2nd DRILL" at 287.147,54.721 h1.14
  text "BOTH" at 314.198,54.721 h1.14
  text "AS SHOWN" at 326.517,54.721 h1.14
  text "NONE" at 340.487,54.721 h1.14
  text "BOARD FINISH:" at 261.62,51.8 h1.52
  text "X" at 284.607,51.673 h1.52
  text "ETCHING" at 287.147,51.673 h1.14
  text "REFER PATTERN MASTER LIST" at 314.198,51.673 h1.14
  text "LEGEND / SCREEN PRINT:" at 281.94,48.752 h1.27
  text "NONE" at 314.198,48.625 h1.14
  text "COMPONENT" at 326.517,48.625 h1.14
  text "SOLDER" at 340.487,48.625 h1.14
  text "X" at 323.977,48.498 h1.52
  text "X" at 337.947,48.498 h1.52
  text "COLOUR:" at 272.161,45.704 h1.27
  text "WHITE" at 287.147,45.577 h1.14
  text "YELLOW" at 314.198,45.577 h1.14
  text "OTHER" at 340.487,45.577 h1.14
  text "X" at 284.607,45.45 h1.52
  text "X" at 284.607,42.529 h1.52
  text "LIQUID PHOTOIMAGEABLE" at 287.147,42.529 h1.14
  text "SCREEN PRINT" at 326.517,42.529 h1.14
  text "MATTE" at 287.147,39.481 h1.14
  text "GLOSS" at 299.847,39.481 h1.14
  text "GREEN" at 314.198,39.481 h1.14
  text "BLUE" at 326.517,39.481 h1.14
  text "G/Y" at 340.487,39.481 h1.14
  text "OTHER" at 351.917,39.481 h1.14
  text "X" at 297.18,39.354 h1.52
  text "SOLDER MASK COLOUR:" at 261.62,36.56 h1.14
  text "BLACK" at 287.147,36.433 h1.14
  text "GREEN" at 299.847,36.433 h1.14
  text "YELLOW" at 314.198,36.433 h1.14
  text "BLUE" at 326.517,36.433 h1.14
  text "OTHER" at 340.487,36.433 h1.14
  text "X" at 284.48,36.306 h1.52
  text "TRACK FINISH:" at 261.62,33.512 h1.52
  text "X" at 284.607,33.385 h1.52
  text "SELECTIVE SOLDER (HASL)" at 287.147,33.385 h1.14
  text "REFLOW SOLDER" at 326.517,33.385 h1.14
  text "SELECTIVE GOLD" at 287.147,30.337 h1.14
  text "um  (AREA" at 314.198,30.337 h1.14
  text "sq. mm)" at 342.011,30.337 h1.14
  text "REFER PATTERN MASTER LIST" at 287.147,27.289 h1.14
  text "OTHER" at 326.517,27.289 h1.14
  text "EDGE BOARD" at 261.62,24.368 h1.52
  text "1.3um HARD GOLD OVER 5um     NICKEL / TIN-NICKEL" at 287.147,24.241 h1.14
  text "CONTACTS:" at 261.62,22.209 h1.52
  text "HARD FINISH GOLDE PLATE" at 287.147,21.193 h1.14
  text "OTHER" at 326.517,21.193 h1.14
  text "AS SHOWN" at 287.147,18.145 h1.14
  text "REFER" at 326.517,18.145 h1.14
  text "PROFILING:" at 261.62,15.097 h1.52
  text "AS DIMENSIONED, MEASURED AND CUT FROM SPECIFIED DATUM." at 287.147,15.097 h1.14
  text "X" at 284.607,14.97 h1.52
  text "REFER PCB BLANK DWG No." at 287.274,12.176 h1.27
  text "USE PROFILE / ROUTE TAPE SUPPLIED (REFER PATTERN MASTER LIST)" at 287.274,9.128 h1.27
  text "SQUARE CUT" at 287.274,6.08 h1.27
  text "N.C. ROUTE" at 305.054,6.08 h1.27
  text "V. SCORE" at 322.834,6.08 h1.27
  text "BLANK" at 340.614,6.08 h1.27
  text "ACCEPTABILITY:" at 261.62,3.413 h1.52
  text "MATERIALS AND WORKMANSHIP FOR ALL PRINTED WIRING BOARDS TO MEET" at 283.845,3.286 h1.27
  text "OR EXCEED THE REQUIREMENTS OF:" at 283.845,0.492 h1.27
  text "IPC-6011/12 AND IPC-A-600E" at 287.401,-2.175 h1.27
  text "1" at 322.961,-2.175 h1.27
  text "2" at 331.851,-2.175 h1.27
  text "X" at 329.184,-2.302 h1.52
  text "X" at 284.734,-2.429 h1.52
  text "3" at 340.741,-4.334 h1.27
  text "UL CERTIFICATION" at 287.401,-5.223 h1.27
  text "AUSTEL" at 322.961,-5.223 h1.27
  text "X" at 284.734,-5.35 h1.52
  text "ML-P-55110F GRP" at 286.893,-8.271 h1.02
  text "A" at 305.181,-8.271 h1.27
  text "B" at 314.071,-8.271 h1.27
  text "AS2546" at 322.961,-8.271 h1.27
  text "OTHER" at 340.741,-8.271 h1.27
  text "ADDITIONAL" at 261.62,-11.192 h1.52
  text "NONE" at 287.401,-11.446 h1.27
  text "SAMPLE PLAN" at 305.181,-11.446 h1.27
  text "MIL-P-55110E SERIAL Nos. PER ORDER" at 322.961,-11.446 h1.27
  text "REQUIREMENTS:" at 261.62,-13.605 h1.52
  text "NONE" at 287.401,-14.494 h1.27
  text "ML-P-55110F GRP" at 304.673,-14.494 h1.02
  text "A" at 322.961,-14.494 h1.27
  text "B" at 331.851,-14.494 h1.27
  text "IPC CLASS:" at 337.82,-14.494 h1.27
  text "1" at 353.314,-14.494 h1.27
  text "2" at 359.664,-14.494 h1.27
  text "3" at 366.014,-14.494 h1.27
  text "QUALITY RELEASE REPORT" at 305.181,-17.542 h1.27
  text "OTHER" at 345.694,-17.542 h1.27
  text "PER ORDER" at 354.203,-17.669 h1.27
  text "X" at 343.027,-17.796 h1.52
  text "NONE" at 305.181,-20.59 h1.27
  text "REQUIRED" at 322.961,-20.59 h1.27
  text "PER ORDER" at 345.821,-20.59 h1.27
  text "ELECTRICAL TEST:" at 261.62,-20.717 h1.52
  text "X" at 320.294,-20.717 h1.52
  text "NONE" at 305.181,-23.638 h1.27
  text "1 SIDE" at 322.834,-23.638 h1.14
  text "2 SIDES" at 334.01,-23.638 h1.14
  text "MIN. PITCH" at 345.694,-23.638 h1.27
  text "0.50mm" at 359.283,-23.638 h1.27
  text "SURFACE MOUNT:" at 261.62,-23.765 h1.52
  text "X" at 331.775,-23.841 h1.52
  text "NONE" at 305.181,-26.686 h1.27
  text "FOIL" at 322.961,-26.686 h1.27
  text "LEGEND" at 334.391,-26.686 h1.27
  text "REFER" at 345.694,-26.686 h1.27
  text "MANUFACTURER'S ID/LOGO:" at 261.62,-26.813 h1.52
  text "ISO9001/AS3901" at 308.991,-29.734 h1.27
  text "NONE" at 345.694,-29.734 h1.27
  text "MANUFACTURER'S ACCREDITATION:" at 261.62,-29.861 h1.52
  text "X" at 306.324,-29.861 h1.52
  text "PER ORDER" at 305.181,-32.782 h1.27
  text "REFER" at 322.961,-32.782 h1.27
  text "PACKAGING AND HANDLING:" at 261.62,-32.909 h1.52
  text "X" at 302.514,-33.036 h1.52
Sheet:
  drawing of 1882 lines, arcs and shapes, not listed
  text "1" at 3.717,207.391 h1.78
  text "2" at 52.756,207.391 h1.78
  text "3" at 102.015,207.391 h1.78
  text "4" at 151.308,207.391 h1.78
  text "5" at 200.584,207.391 h1.78
  text "6" at 249.606,207.391 h1.78
  text "7" at 299.136,207.391 h1.78
  text "8" at 348.158,207.391 h1.78
  text "A" at -18.415,173.406 h1.78
  text "A" at 370.205,173.406 h1.78
  text "B" at -18.415,102.794 h1.78
  text "B" at 370.205,102.794 h1.78
  text "C" at -18.415,32.182 h1.78
  text "C" at 370.205,32.182 h1.78
  text "D" at -18.415,-37.922 h1.78
  text "D" at 370.205,-37.922 h1.78
  text "ENGINEER:" at 255.27,-38.1 h1.14
  text "TITLE:" at 293.37,-38.1 h1.14
  text "PCB DESIGNER:" at 255.27,-45.593 h1.14
  text "DATE:" at 255.27,-53.34 h1.14
  text "PART NO.:" at 293.37,-53.34 h1.14
  text "REV:" at 346.71,-53.34 h1.14
  text "Altium Limited" at 222.25,-55.88 h1.78
  text ".PRINT_DATE" at 256.54,-56.388 h1.78
  text "12a Rodborough Rd" at 222.25,-58.42 h1.78
  text "Frenchs Forest" at 222.25,-60.96 h1.78
  text "FILE NAME:" at 255.27,-60.96 h1.14
  text "DWG NO:" at 293.37,-60.96 h1.14
  text "SCALE:" at 346.71,-60.96 h1.14
  text "NSW 2086" at 222.25,-63.5 h1.78
  text ".PCB_FILE_NAME_NO_PATH" at 256.54,-64.008 h1.78
  text "1" at 3.717,-69.469 h1.78
  text "2" at 52.756,-69.469 h1.78
  text "3" at 102.015,-69.469 h1.78
  text "4" at 151.308,-69.469 h1.78
  text "5" at 200.584,-69.469 h1.78
  text "6" at 249.606,-69.469 h1.78
  text "7" at 299.136,-69.469 h1.78
  text "8" at 348.158,-69.469 h1.78
Drill Drawing:
  text ".Legend" at 0,-8 h0.75

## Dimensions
0,0 to 69,0 on Dimensions
0,0 to 0.001,77 on Dimensions
34.5,-69.801 to 34.5,84 on Dimensions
